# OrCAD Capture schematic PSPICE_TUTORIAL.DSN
size A
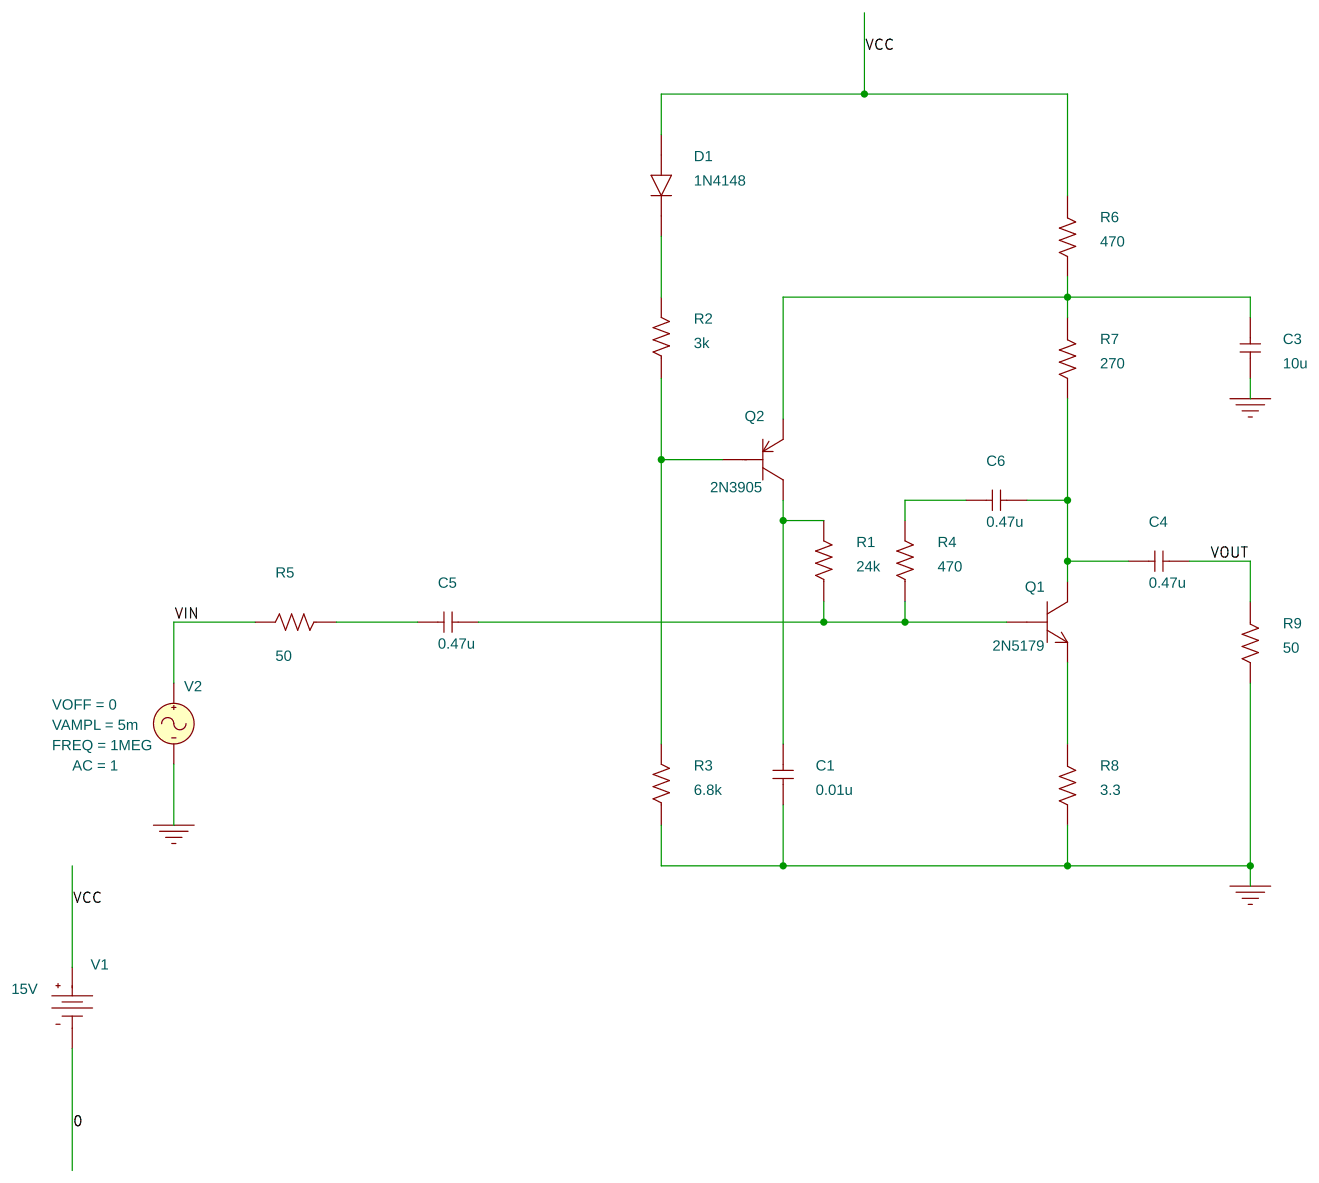
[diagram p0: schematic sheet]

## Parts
C1  0.01u  [cap196]
C3  10u  [cap196]
C4  0.47u  [RAD/CK05]
C5  0.47u  [RAD/CK05]
C6  0.47u  [RAD/CK05]
D1  1N4148  [dax2do35]
Q1  2N5179  [TO72]
Q2  2N3905  [TO92]
R1  24k  [AXRC05]
R2  3k  [AXRC05]
R3  6.8k  [AXRC05]
R4  470  [AXRC05]
R5  50  [AXRC05]
R6  470  [AXRC05]
R7  270  [AXRC05]
R8  3.3  [AXRC05]
R9  50  [AXRC05]
V1  VDC
V2  VSIN

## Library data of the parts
C1 C3 = C
C4-C6 = C: AppProp: InductiveSlave:SRF;SRF:4.6430e+5;PrevCap:0.47u;PrevESL:250n; ESL: 250n; ESR: 25m; Tolerance: 10
D1 = 1N4148
Q1 = 2N5179
Q2 = 2N3905
R1-R9 = R
V1 = VDC: DC: 15V
V2 = VSIN: AC: 1; AppProp: Sine$Voltage$0$-1; DC: 0; FREQ: 1MEG; VAMPL: 5m; VOFF: 0

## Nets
VCC: D1.2(AN) R6.1 V1.0(+)
VIN: R5.2 V2.1(+)
0: C1.1 C3.2 R3.1 R8.2 R9.2 V1.1(-) V2.2(-)
VOUT: C4.2 R9.1
N01718: C5.1 R5.1
N01722: C5.2 Q1.2(B) R1.1 R4.1
N01750: C6.1 R4.2
N01757: C4.1 C6.2 Q1.3(C) R7.2
N01772: C3.1 Q2.1(E) R6.2 R7.1
N01806: D1.1(CAT) R2.2
N01810: Q2.2(B) R2.1 R3.2
N01823: C1.2 Q2.3(C) R1.2
N01884: Q1.1(E) R8.1
